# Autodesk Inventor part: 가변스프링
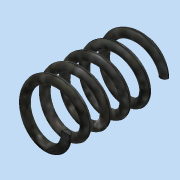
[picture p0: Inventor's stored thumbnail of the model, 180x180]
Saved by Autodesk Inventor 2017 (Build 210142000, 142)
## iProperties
Part Number: 가변스프링
Material: 강철
Document SubType Name: Modeling
Designer: 00-00
Density: 7.85 g/cm^3
Appearance: 플레이트
Mass: 4.5633 g
Surface Area: 11.8528 cm^2
Volume: 0.581313 cm^3
Author: 00-00
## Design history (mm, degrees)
sketch "스케치1"
  geometry: L1 (0, 0)-(6, 0); L2 (6, 0)-(6, 23.5); L3 (6, 23.5)-(0, 23.5); L4 (0, 23.5)-(0, 0); C1 r 1 at (6, 0)
  constraints: 8 end point, 2 parallel, 1 centre point, 1 coincident, 1 horizontal, 1 perpendicular
  dimensions: "d0" = 23.5 distance of L3.end L1.start (derived); "d1" = 6 distance of L2.end L3.end; "d2" = 2 diameter of C1
feature "코일1" sketch "스케치1" pitch "d3" = 23.5 (= d0); turns "d5" = 5; dims "d4" = 23.5 (= d0), "d6" = 0, angle "d7" = 90 deg, angle "d8" = 90 deg, "d9" = 0, "d10" = 0
sketch "스케치2"
  geometry: L1 (0, 15.313)-(23.5, 15.313); L2 (23.5, 15.313)-(23.5, -15.313); L3 (23.5, -15.313)-(0, -15.313); L4 (0, -15.313)-(0, 15.313); 2 further points
  constraints: 8 end point, 2 parallel, 1 coincident, 1 horizontal, 1 midpoint, 1 perpendicular
  dimensions: "d11" = 23.5 distance of L2.end L3.end (= d0); "d14" = 30.62624 distance of L1.end L2.end
extrude "돌출2" sketch "스케치2" stored distance "d15" = 20; taper "d16" = 0 deg
node "솔리드1"
